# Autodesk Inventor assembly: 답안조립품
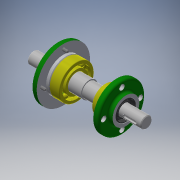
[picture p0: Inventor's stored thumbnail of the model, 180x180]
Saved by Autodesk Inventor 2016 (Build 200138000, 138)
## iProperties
Created: 2019-01
Part Number: 답안조립품
Material: 일반
Document SubType Name: Assembly
Designer: USER
Author: USER
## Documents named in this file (10)
- C:\Users\USER\Desktop\490107V1009\답안조립품.iam
- C:\Users\USER\Desktop\490107V1009\본체.ipt
- C:\Users\USER\Desktop\490107V1009\앞커버.ipt
- C:\Users\USER\Desktop\490107V1009\뒤커버.ipt
- C:\Users\USER\Desktop\490107V1009\베어링 6205.ipt
- C:\Users\USER\Desktop\490107V1009\베어링 6203.ipt
- C:\Users\USER\Desktop\490107V1009\축.ipt
- C:\Users\USER\Desktop\490107V1009\오일 실 25 38 8.ipt
- C:\Users\USER\Desktop\490107V1009\오일 실 17 30 8.ipt
- C:\Users\USER\Desktop\490107V1009\볼트 M4.ipt
